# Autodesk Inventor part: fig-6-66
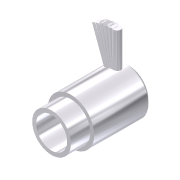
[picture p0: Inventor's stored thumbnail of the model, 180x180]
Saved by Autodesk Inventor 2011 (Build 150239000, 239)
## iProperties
Shininess: 77.0
Angle Display Precision: 2
Document Length Units: 11269
Document Angle Units: 11279
Document Time Units: 11290
Document Mass Units: 11283
Document Length Units Precision: 3
Document Angle Units Precision: 2
Compacted: True
Created: 2001-12
Part Number: fig-6-66
Document SubType Name: Modeling
Designer: Renu Muthoo
Density: 1 g/cm^3
Density: 0.0
Volumn: 0.0
Area: 0.0
PropertySet Name: Model Information
Control State: 0
Master: False
Checked Out: False
Author: Renu Muthoo
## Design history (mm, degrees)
sketch "Sketch2"
  geometry: L1 (-9.573, -4.327)-(-9.573, -5.327); L2 (-9.573, -5.327)-(-4.573, -5.327); L3 (-4.573, -5.327)-(-4.573, -6.327); L4 (-4.573, -6.327)-(9.427, -6.327); L5 (9.427, -6.327)-(10.427, -5.327); L6 (10.427, -5.327)-(10.427, -4.327); L7 (10.427, -4.327)-(-9.573, -4.327); L8 (-13.687, -0.327)-(14, -0.327)
  constraints: 16 end point, 5 parallel, 1 perpendicular, 1 vertical
  dimensions: "d9" = 20 distance of L6.end L1.start; "d10" = 5 distance of L1.end L2.end; "d11" = 12 diameter of L4 L8; "d12" = 10 diameter of L2 L8; "d13" = 8 diameter of L7 L8; "d14" = 45 deg angle of L5 L4; "d15" = 1 horizontal distance of L5.end L4.end
revolve "Revolution2" sketch "Sketch2" stored, may be unused: angle "d16" = 90 deg
workplane "Work Plane1"
workplane "Work Plane2"
sketch "Sketch3"
  geometry: L1 (-4, 8)-(4, 8) reference; C1 r 1 at (-0.098, 5)
  constraints: 1 centre point
  dimensions: "d18" = 3 distance from line of L1 C1.centre; "d19" = 2 diameter of C1
extrude "Extrusion1" join sketch "Sketch3" distance "d20" = 10; taper "d21" = 0 deg
pattern_circular "Circular Pattern3" dims angle "d29" = 20 deg
body "Solid1"
other parameters: "d17" = -1
